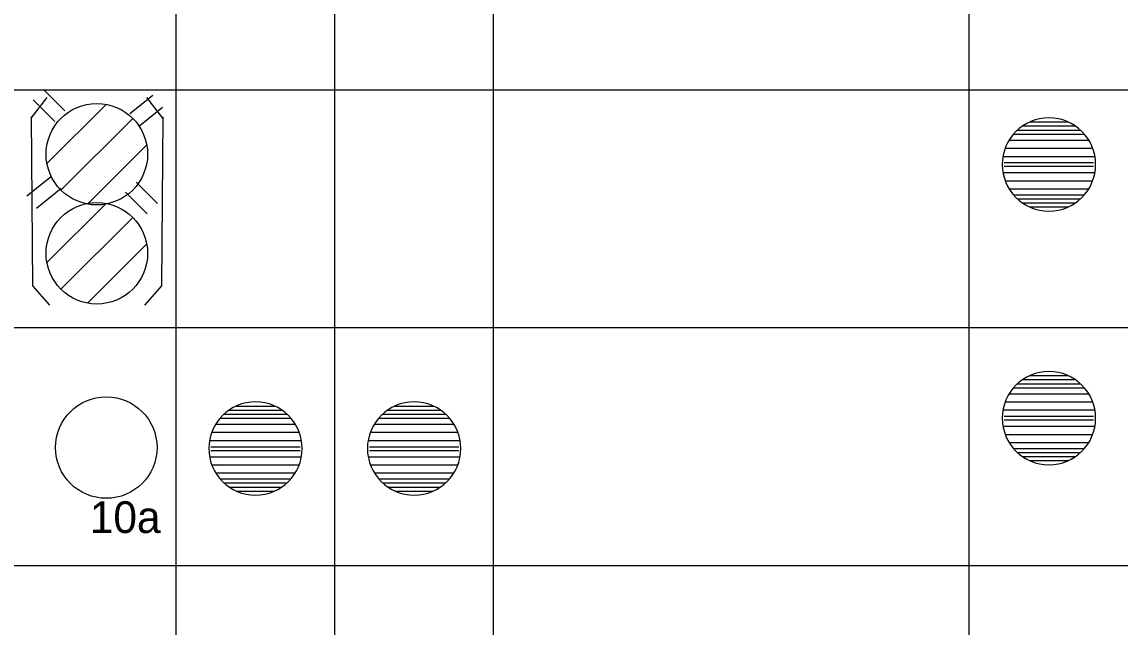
# Model space of a CAD drawing. Extents: x -28 to 822, y 61 to 665.
# Drawn here: x 53.4 to 122.6, y 182.9 to 221 of the extents above; entities that cross this region are included whole.
import ezdxf

# ---------------------------------------------------------------- set-up
doc = ezdxf.new("R2010")
doc.units = 0
doc.layers.add('KOLEJIŠTĚ', color=7, linetype='Continuous')

# ---------------------------------------------------------------- blocks, each defined once
blk = doc.blocks.new('HR6')
for p, q in [((-1.555, 1.695), (1.555, 1.695)), ((-1.304, 1.895), (1.304, 1.895)), ((-0.95, 2.095), (0.95, 2.095)), ((-1.962, 1.2), (1.962, 1.2)), ((-1.748, 1.495), (1.748, 1.495)), ((-2.156, 0.8), (2.156, 0.8)), ((-2.265, 0.4), (2.265, 0.4)), ((-2.2, 0.09), (2.2, 0.09)), ((-2.265, -0.4), (2.265, -0.4)), ((-2.2, -0.09), (2.2, -0.09)), ((-2.156, -0.8), (2.156, -0.8)), ((-1.962, -1.2), (1.962, -1.2)), ((-1.748, -1.495), (1.748, -1.495)), ((-1.555, -1.695), (1.555, -1.695)), ((-1.304, -1.895), (1.304, -1.895)), ((-0.95, -2.095), (0.95, -2.095))]:
    blk.add_line(p, q)
for start, end in [(0, 180), (180, 0)]:
    blk.add_arc((0, 0), 2.3, start, end)
blk = doc.blocks.new('ZT75')
at = {"xscale": 0.8, "yscale": 0.8000000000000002}
blk.add_blockref('HR6', (0, 0), dxfattribs=at)
blk = doc.blocks.new('ZT94')
at = {"xscale": 0.6400000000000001, "yscale": 0.6400000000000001}
blk.add_blockref('HR6', (2.5, 2.5), dxfattribs=at)
blk = doc.blocks.new('ZT95')
for p, q in [((2.793, 4.073), (0.927, 2.207)), ((3.631, 3.631), (1.369, 1.369)), ((4.073, 2.793), (2.207, 0.927))]:
    blk.add_line(p, q)
blk.add_circle((2.5, 2.5), 1.6)

msp = doc.modelspace()

# ---------------------------------------------------------------- linework, layer by layer
for p, q in [((63.116, 381.738), (63.116, 111.738)), ((73.116, 381.738), (73.116, 111.738)), ((113.116, 381.738), (113.116, 111.738)), ((83.116, 336.738), (83.116, 111.738)), ((5.068, 216.738), (540.616, 216.738)), ((56.129, 215.408), (54.777, 216.759)), ((54.013, 214.959), (55.011, 216.262)), ((55.486, 214.746), (54.121, 216.11)), ((60.227, 215.242), (61.675, 216.4)), ((62.303, 214.959), (61.305, 216.262)), ((60.844, 214.482), (62.291, 215.64)), ((54.013, 215.035), (54.09, 204.376)), ((62.303, 215.035), (62.226, 204.376)), ((53.732, 210.046), (55.294, 211.295)), ((54.338, 209.278), (55.9, 210.527)), ((61.974, 209.562), (60.616, 210.921)), ((61.325, 208.906), (59.954, 210.278)), ((54.09, 204.376), (55.164, 203.149)), ((62.226, 204.376), (61.151, 203.149)), ((5.068, 201.738), (540.616, 201.738)), ((5.068, 201.738), (540.616, 201.738)), ((5.068, 201.738), (540.616, 201.738)), ((54.092, 201.738), (540.616, 201.738)), ((5.068, 186.738), (295.616, 186.738))]:
    msp.add_line(p, q)
msp.add_circle((58.737, 194.173), 3.2)

# ---------------------------------------------------------------- block references
at = {"layer": 'KOLEJIŠTĚ'}
for name, p, xscale, yscale in [('ZT95', (53.143, 207.677), 2, 2), ('ZT75', (118.157, 212.031), 1.600000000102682, 1.600000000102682), ('ZT95', (53.143, 201.428), 2, 2), ('ZT75', (118.157, 196.031), 1.600000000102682, 1.600000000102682), ('ZT94', (63.143, 189.111), 2, 2), ('ZT94', (73.143, 189.111), 2, 2)]:
    msp.add_blockref(name, p, dxfattribs=dict(at, xscale=xscale, yscale=yscale))

# ---------------------------------------------------------------- texts
msp.add_text('10a', height=2).set_placement((57.698, 188.784))

doc.saveas('drawing.dxf')
